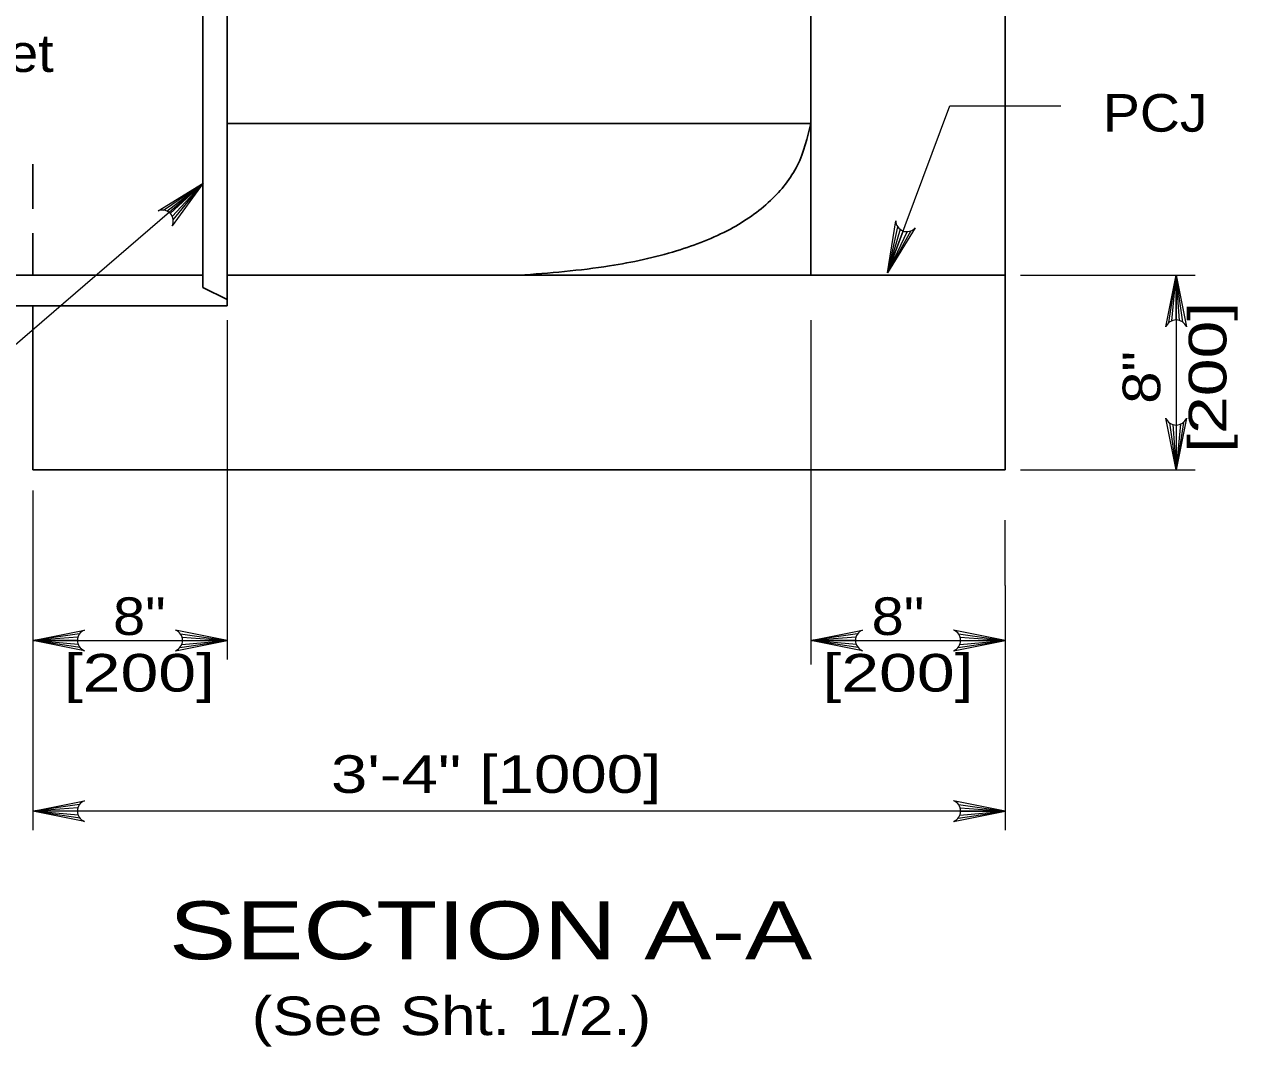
# Model space of a CAD drawing. Extents: x 758.3 to 792.3, y 849.7 to 893.7.
# Drawn here: x 764.35 to 769.38, y 861.2 to 865.44 of the extents above; entities that cross this region are included whole.
import ezdxf
from ezdxf.enums import TextEntityAlignment as Align

# ---------------------------------------------------------------- set-up
doc = ezdxf.new("R2010")
doc.units = 0
doc.header["$LTSCALE"] = 0.062
doc.linetypes.add('MEDIUM_DASHED', pattern=[4.5, 3, -1.5])
doc.layers.add('1', color=7, linetype='Continuous', lineweight=13)

msp = doc.modelspace()

# ---------------------------------------------------------------- linework, layer by layer
at = {"layer": '1', "lineweight": 25}
for p, q in [((765.19, 868.47125), (765.19, 864.39992)), ((768.41517, 867.81617), (768.41517, 863.59375)), ((767.60892, 867.54017), (767.60892, 864.39992)), ((765.08925, 865.71008), (765.08925, 864.3495)), ((767.60892, 865.02983), (765.19, 865.02983)), ((765.19, 864.39992), (765.19, 864.27392)), ((768.41517, 864.39992), (765.19, 864.39992)), ((765.19, 864.29917), (765.08925, 864.3495)), ((765.19, 864.27392), (763.47667, 864.27392)), ((768.41517, 863.59375), (764.38375, 863.59375))]:
    msp.add_line(p, q, dxfattribs=at)
at = {"layer": '1', "linetype": 'MEDIUM_DASHED', "lineweight": 25}
msp.add_line((764.38375, 864.86133), (764.38375, 864.40108), dxfattribs=at)
at = {"layer": '1'}
for p, q in [((764.92583, 864.6705), (765.09033, 864.7815)), ((764.93975, 864.66625), (765.09033, 864.7815)), ((764.95408, 864.65583), (765.09033, 864.7815)), ((764.96192, 864.64442), (765.09033, 864.7815)), ((764.96617, 864.63008), (765.09033, 864.7815)), ((767.96858, 864.60158), (767.92692, 864.41025)), ((767.97892, 864.59075), (767.92692, 864.41025)), ((767.99108, 864.58417), (767.92692, 864.41025)), ((768.023, 864.58392), (767.92692, 864.41025)), ((768.00858, 864.58133), (767.92692, 864.41025)), ((768.47792, 864.39992), (769.20183, 864.39992)), ((769.09317, 864.20375), (769.12317, 864.39992)), ((769.10575, 864.21117), (769.12317, 864.39992)), ((769.12317, 864.21458), (769.12317, 864.39992)), ((769.13692, 864.21258), (769.12317, 864.39992)), ((769.15033, 864.206), (769.12317, 864.39992)), ((769.12317, 864.39992), (769.12317, 863.59375)), ((765.19, 864.21358), (765.19, 862.80708)), ((767.60892, 864.21358), (767.60892, 863.06492)), ((769.09608, 863.78758), (769.12317, 863.59375)), ((769.1095, 863.78108), (769.12317, 863.59375)), ((769.15317, 863.78992), (769.12317, 863.59375)), ((769.14058, 863.7825), (769.12317, 863.59375)), ((769.12317, 863.77908), (769.12317, 863.59375)), ((768.47792, 863.59375), (769.20183, 863.59375)), ((764.38375, 863.50708), (764.38375, 862.09908)), ((768.41517, 863.11275), (768.41517, 863.38383)), ((768.41517, 863.11275), (768.41517, 862.09908)), ((767.60892, 863.06642), (767.60892, 862.78542)), ((764.57767, 862.91283), (764.38375, 862.88575)), ((764.99617, 862.91283), (765.19, 862.88575)), ((767.80283, 862.91283), (767.60892, 862.88575)), ((768.22125, 862.91283), (768.41517, 862.88575)), ((764.57108, 862.89942), (764.38375, 862.88575)), ((764.56908, 862.88575), (764.38375, 862.88575)), ((764.5725, 862.86833), (764.38375, 862.88575)), ((764.57992, 862.85575), (764.38375, 862.88575)), ((764.99383, 862.85575), (765.19, 862.88575)), ((765.00125, 862.86833), (765.19, 862.88575)), ((765.00275, 862.89942), (765.19, 862.88575)), ((765.00475, 862.88575), (765.19, 862.88575)), ((767.79625, 862.89942), (767.60892, 862.88575)), ((767.79425, 862.88575), (767.60892, 862.88575)), ((767.79767, 862.86833), (767.60892, 862.88575)), ((767.80508, 862.85575), (767.60892, 862.88575)), ((768.219, 862.85575), (768.41517, 862.88575)), ((768.22642, 862.86833), (768.41517, 862.88575)), ((768.22783, 862.89942), (768.41517, 862.88575)), ((768.22983, 862.88575), (768.41517, 862.88575)), ((764.57767, 862.20483), (764.38375, 862.17775)), ((768.22125, 862.20483), (768.41517, 862.17775)), ((764.57108, 862.19142), (764.38375, 862.17775)), ((764.56908, 862.17775), (764.38375, 862.17775)), ((764.5725, 862.16033), (764.38375, 862.17775)), ((764.57992, 862.14775), (764.38375, 862.17775)), ((768.41517, 862.17775), (764.38375, 862.17775)), ((768.219, 862.14775), (768.41517, 862.17775)), ((768.22642, 862.16033), (768.41517, 862.17775)), ((768.22783, 862.19142), (768.41517, 862.17775)), ((768.22983, 862.17775), (768.41517, 862.17775))]:
    msp.add_line(p, q, dxfattribs=at)
for points in [[(767.92692, 864.41025), (768.1855, 865.10258), (768.64558, 865.10258)], [(765.09033, 864.7815), (763.36183, 863.29267), (763.17392, 863.29267)], [(764.90392, 864.66775), (765.09033, 864.7815), (764.96192, 864.60475)], [(768.04125, 864.59633), (767.92692, 864.41025), (767.96092, 864.626)], [(769.08033, 864.18575), (769.12317, 864.39992), (769.166, 864.18575)], [(769.166, 863.80792), (769.12317, 863.59375), (769.08033, 863.80792)], [(764.59792, 862.84292), (764.38375, 862.88575), (764.59792, 862.92858)], [(764.97583, 862.84292), (765.19, 862.88575), (764.97583, 862.92858)], [(767.82308, 862.84292), (767.60892, 862.88575), (767.82308, 862.92858)], [(768.201, 862.84292), (768.41517, 862.88575), (768.201, 862.92858)], [(764.38375, 862.88575), (764.94408, 862.88575), (765.19, 862.88575)], [(767.60892, 862.88575), (768.15733, 862.88575), (768.41517, 862.88575)], [(764.59792, 862.13492), (764.38375, 862.17775), (764.59792, 862.22058)], [(768.201, 862.13492), (768.41517, 862.17775), (768.201, 862.22058)]]:
    msp.add_lwpolyline(points, dxfattribs=at)
at = {"layer": '1', "lineweight": 25}
for points in [[(765.08925, 864.39992), (763.47667, 864.39992), (763.47667, 864.27392)], [(764.38375, 864.27392), (764.38375, 863.65133), (764.38375, 863.59375)]]:
    msp.add_lwpolyline(points, dxfattribs=at)
at = {"layer": '1'}
for centre, start, end in [((764.92023, 864.62449), 334.77826, 110.60438), ((768.00702, 864.62744), 181.82309, 317.64922), ((769.12323, 864.16845), 22.08782, 157.91395), ((769.12314, 863.82518), 202.08782, 337.91395), ((764.61522, 862.88577), 112.08782, 247.91395), ((764.95858, 862.88577), 292.08605, 67.91218), ((767.84037, 862.88576), 112.08782, 247.91395), ((768.18372, 862.88576), 292.08605, 67.91218), ((764.61522, 862.17776), 112.08782, 247.91395), ((768.18372, 862.17776), 292.08605, 67.91218)]:
    msp.add_arc(centre, 0.04623, start, end, dxfattribs=at)
at = {"layer": '1', "lineweight": 25}
msp.add_spline([(767.60892, 865.02983), (767.55325, 864.85617), (767.442, 864.71008), (767.27533, 864.592), (767.05283, 864.50158), (766.775, 864.439), (766.3995, 864.39992)], degree=3, dxfattribs=at)

# ---------------------------------------------------------------- texts
at = {"layer": '1'}
for s, height, width, p in [('Outlet', 0.156, 1.1, (763.85817, 865.24342)), ('PCJ', 0.156, 1.1, (768.81983, 864.99575)), ('3\'-4" [1000]', 0.156, 1.3, (765.61992, 862.25317)), ('SECTION A-A', 0.24, 1.3, (764.94867, 861.56333)), ('(See Sht. 1/2.)', 0.16, 1.2, (765.29158, 861.24833))]:
    msp.add_text(s, height=height, dxfattribs=dict(at, width=width)).set_placement(p)
for s, width, p in [('[200]', 1.35, (769.33142, 863.97671)), ('8"', 1.15, (769.05742, 863.97662))]:
    msp.add_text(s, height=0.156, rotation=90, dxfattribs=dict(at, width=width)).set_placement(p, align=Align.CENTER)
for s, width, p in [('8"', 1.15, (764.82579, 862.90808)), ('8"', 1.15, (767.97012, 862.90808)), ('[200]', 1.35, (764.82587, 862.67342)), ('[200]', 1.35, (767.97021, 862.67342))]:
    msp.add_text(s, height=0.156, dxfattribs=dict(at, width=width)).set_placement(p, align=Align.CENTER)

doc.saveas('drawing.dxf')
